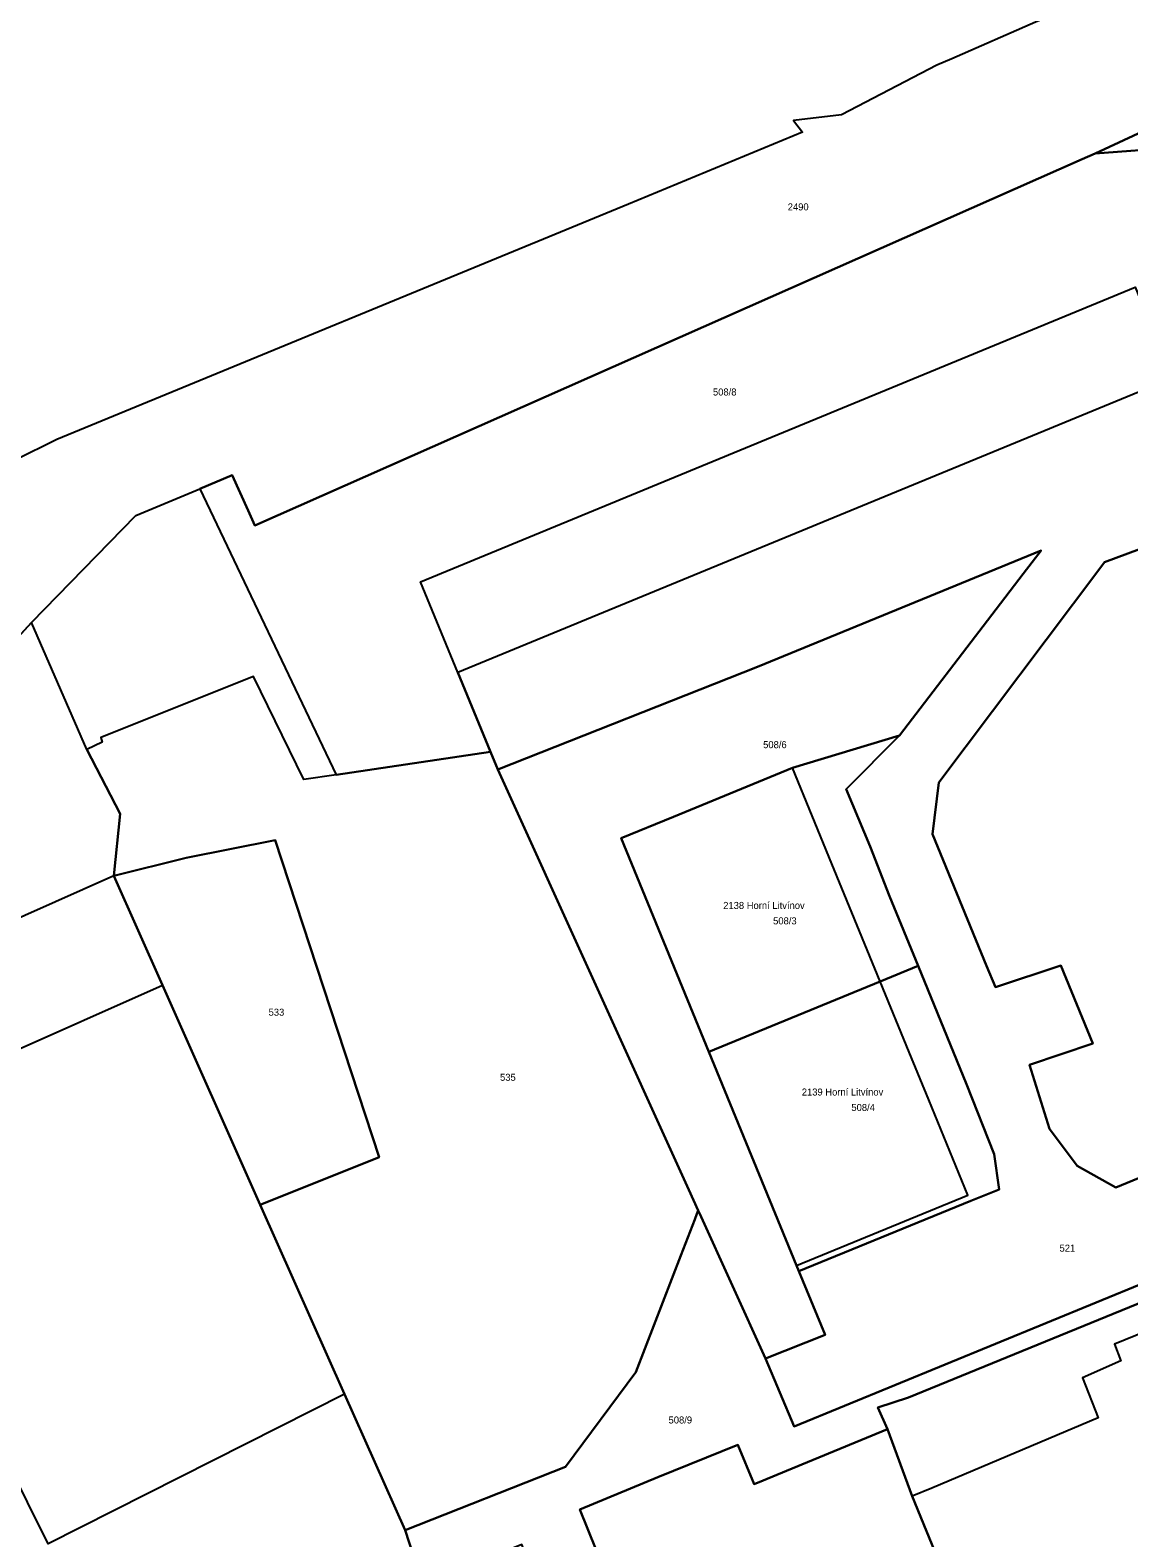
# Model space of a CAD drawing. Extents: x -792094 to -791524, y -979074 to -977761.
# Drawn here: x -791873.9 to -791795.7, y -978554.8 to -978447.5 of the extents above; entities that cross this region are included whole.
import ezdxf

# ---------------------------------------------------------------- set-up
doc = ezdxf.new("R2010")
doc.units = 0
doc.layers.add('katastr', color=7, linetype='Continuous')

msp = doc.modelspace()

# ---------------------------------------------------------------- linework, layer by layer
at = {"layer": 'katastr'}
for points in [[(-791795.52, -978444.13), (-791797.38, -978444.82), (-791798.74, -978445.45), (-791799.89, -978445.93), (-791801.55, -978446.63), (-791802.38, -978446.98), (-791808.34, -978449.57), (-791809.4, -978450.03), (-791816.2, -978453.56), (-791819.61, -978453.96), (-791818.96, -978454.81), (-791831.35, -978459.92), (-791872.03, -978476.67), (-791875, -978478.14)], [(-791881.47, -978498.04), (-791873.83, -978489.7), (-791866.4, -978482.08), (-791861.86, -978480.18), (-791859.55, -978479.21), (-791858.41, -978481.73), (-791857.93, -978482.79), (-791799.08, -978456.73), (-791798.15, -978456.32), (-791780.49, -978448.1)], [(-791780.49, -978448.1), (-791798.15, -978456.32), (-791792.44, -978455.89)], [(-791792.64, -978472.3), (-791843.49, -978493.26), (-791841.16, -978498.91), (-791840.65, -978500.15), (-791822.17, -978492.85), (-791801.99, -978484.56), (-791803.27, -978486.24), (-791805.49, -978489.15), (-791812.06, -978497.74), (-791815.87, -978501.56), (-791814.16, -978505.64), (-791812.78, -978509.16), (-791810.75, -978514.13), (-791808.68, -978519.19), (-791807.31, -978522.56), (-791805.34, -978527.53), (-791804.98, -978530.04), (-791806.99, -978530.86), (-791819.22, -978535.87), (-791817.36, -978540.4), (-791821.61, -978542.07), (-791819.57, -978546.91), (-791769.41, -978526.33)], [(-791792.51, -978483.54), (-791797.47, -978485.4), (-791797.82, -978485.86), (-791809.28, -978501.08), (-791809.72, -978504.77), (-791805.88, -978514.12), (-791805.24, -978515.64), (-791800.59, -978514.11), (-791798.32, -978519.66), (-791802.81, -978521.18), (-791801.39, -978525.72), (-791799.42, -978528.37), (-791796.68, -978529.91), (-791780.67, -978523.32)], [(-791780.67, -978523.32), (-791796.68, -978529.91), (-791799.42, -978528.37), (-791801.39, -978525.72), (-791802.81, -978521.18), (-791798.32, -978519.66), (-791800.59, -978514.11), (-791805.24, -978515.64), (-791805.88, -978514.12), (-791809.72, -978504.77), (-791809.28, -978501.08), (-791797.82, -978485.86), (-791797.47, -978485.4), (-791792.51, -978483.54)], [(-791875, -978589.26), (-791840.39, -978574.85), (-791842.83, -978568.27), (-791842.3, -978568.03), (-791845.28, -978560.36), (-791847.25, -978554.3), (-791851.56, -978544.62), (-791857.55, -978531.14), (-791864.51, -978515.5), (-791867.96, -978507.73), (-791867.52, -978503.3), (-791869.9, -978498.73), (-791873.83, -978489.7), (-791881.47, -978498.04)], [(-791769.41, -978526.33), (-791819.57, -978546.91), (-791821.61, -978542.07), (-791826.31, -978531.72), (-791826.39, -978531.54), (-791826.48, -978531.79), (-791826.64, -978532.19), (-791827.63, -978534.75), (-791830.84, -978543.04), (-791835.83, -978549.79), (-791847.25, -978554.3), (-791845.28, -978560.36)], [(-791833.68, -978555.64), (-791834.82, -978552.82), (-791829.26, -978550.53), (-791823.58, -978548.22), (-791822.41, -978551.01), (-791821.77, -978550.75), (-791820.1, -978550.06), (-791812.93, -978547.11), (-791813.62, -978545.56), (-791811.43, -978544.86), (-791774.63, -978529.81)], [(-791789.81, -978538.22), (-791796.77, -978541.06), (-791796.33, -978542.25), (-791799.04, -978543.45), (-791797.94, -978546.29), (-791809.76, -978551.3), (-791811.16, -978551.87), (-791807.29, -978561.32)]]:
    msp.add_lwpolyline(points, dxfattribs=at)
for points in [[(-791852.16, -978500.54), (-791841.16, -978498.91), (-791843.49, -978493.26), (-791846.16, -978486.79), (-791795.31, -978465.83), (-791792.64, -978472.3), (-791790.63, -978473.64), (-791787.06, -978473.52), (-791785.07, -978470.7), (-791784.46, -978468.6), (-791784.9, -978465.65), (-791787.73, -978459.17), (-791790.15, -978456.83), (-791792.44, -978455.89), (-791798.15, -978456.32), (-791799.08, -978456.73), (-791857.93, -978482.79), (-791858.41, -978481.73), (-791859.55, -978479.21), (-791861.86, -978480.18)], [(-791817.36, -978540.4), (-791819.22, -978535.87), (-791819.39, -978535.45), (-791825.63, -978520.24), (-791831.87, -978505.05), (-791828.14, -978503.52), (-791826.93, -978503.02), (-791819.69, -978500.04), (-791812.06, -978497.74), (-791805.49, -978489.15), (-791803.27, -978486.24), (-791801.99, -978484.56), (-791822.17, -978492.85), (-791840.65, -978500.15), (-791827.05, -978530.08), (-791826.39, -978531.54), (-791826.31, -978531.72), (-791821.61, -978542.07)], [(-791857.55, -978531.14), (-791851.56, -978544.62), (-791847.25, -978554.3), (-791835.83, -978549.79), (-791830.84, -978543.04), (-791827.63, -978534.75), (-791826.64, -978532.19), (-791826.48, -978531.79), (-791826.39, -978531.54), (-791827.05, -978530.08), (-791840.65, -978500.15), (-791841.16, -978498.91), (-791852.16, -978500.54), (-791854.45, -978500.88), (-791858.03, -978493.54), (-791868.89, -978497.87), (-791868.79, -978498.21), (-791869.9, -978498.73), (-791867.52, -978503.3), (-791867.96, -978507.73), (-791862.83, -978506.45), (-791856.48, -978505.18), (-791849.09, -978527.74)], [(-791815.87, -978501.56), (-791812.06, -978497.74), (-791819.69, -978500.04), (-791826.93, -978503.02), (-791828.14, -978503.52), (-791831.87, -978505.05), (-791825.63, -978520.24), (-791813.45, -978515.24), (-791810.75, -978514.13), (-791812.78, -978509.16), (-791814.16, -978505.64)], [(-791816.88, -978506.87), (-791819.69, -978500.04), (-791826.93, -978503.02), (-791828.14, -978503.52), (-791831.87, -978505.05), (-791825.63, -978520.24), (-791813.45, -978515.24), (-791815.46, -978510.33)], [(-791856.48, -978505.18), (-791862.83, -978506.45), (-791867.96, -978507.73), (-791864.51, -978515.5), (-791857.55, -978531.14), (-791849.09, -978527.74)], [(-791895.64, -978523.92), (-791904.12, -978527.7), (-791898.74, -978539.79), (-791896.4, -978545.04), (-791894.73, -978548.78), (-791888.92, -978561.85), (-791886.45, -978560.75), (-791876.4, -978583.26), (-791842.83, -978568.27), (-791842.3, -978568.03), (-791845.28, -978560.36), (-791847.25, -978554.3), (-791851.56, -978544.62), (-791872.65, -978555.27), (-791887.35, -978525.65), (-791864.51, -978515.5), (-791867.96, -978507.73), (-791890.94, -978517.95), (-791889.5, -978521.19)], [(-791825.63, -978520.24), (-791819.39, -978535.45), (-791819.22, -978535.87), (-791806.99, -978530.86), (-791804.98, -978530.04), (-791805.34, -978527.53), (-791807.31, -978522.56), (-791808.68, -978519.19), (-791810.75, -978514.13), (-791813.45, -978515.24)], [(-791809.99, -978523.66), (-791811.37, -978520.28), (-791813.45, -978515.24), (-791825.63, -978520.24), (-791819.39, -978535.45), (-791807.2, -978530.44)], [(-791771.33, -978535.31), (-791774.63, -978529.81), (-791811.43, -978544.86), (-791813.62, -978545.56), (-791812.93, -978547.11), (-791811.16, -978551.87), (-791807.29, -978561.32), (-791796.91, -978557.01), (-791797.13, -978556.47), (-791790.51, -978553.7), (-791790.37, -978554.03), (-791785.57, -978552.04), (-791785.71, -978551.71), (-791779.05, -978548.94), (-791778.82, -978549.5), (-791768.52, -978545.22), (-791771.39, -978535.79), (-791771.11, -978535.68)], [(-791833.68, -978555.64), (-791838.1, -978557.39), (-791838.94, -978555.31), (-791842.27, -978556.66), (-791841.45, -978558.73), (-791845.28, -978560.36), (-791842.3, -978568.03), (-791839.7, -978574.57), (-791824.14, -978568.2), (-791807.29, -978561.32), (-791811.16, -978551.87), (-791812.93, -978547.11), (-791820.1, -978550.06), (-791821.77, -978550.75), (-791822.41, -978551.01), (-791823.58, -978548.22), (-791829.26, -978550.53), (-791834.82, -978552.82)], [(-791807.29, -978561.32), (-791811.16, -978551.87), (-791812.93, -978547.11), (-791820.1, -978550.06), (-791821.77, -978550.75), (-791822.41, -978551.01), (-791823.58, -978548.22), (-791829.26, -978550.53), (-791834.82, -978552.82), (-791833.68, -978555.64), (-791838.1, -978557.39), (-791838.94, -978555.31), (-791842.27, -978556.66), (-791841.45, -978558.73), (-791845.28, -978560.36), (-791842.3, -978568.03), (-791839.7, -978574.57), (-791824.14, -978568.2)]]:
    msp.add_lwpolyline(points, close=True, dxfattribs=at)

# ---------------------------------------------------------------- texts
for s, p in [('2490', (-791820.02, -978460.37)), ('508/8', (-791825.34, -978473.54)), ('508/6', (-791821.77, -978498.64)), ('2138 Horní Litvínov', (-791824.61, -978510.08)), ('508/3', (-791821.06, -978511.18)), ('533', (-791856.96, -978517.68)), ('535', (-791840.49, -978522.31)), ('2139 Horní Litvínov', (-791819.02, -978523.36)), ('508/4', (-791815.49, -978524.46)), ('521', (-791800.68, -978534.47)), ('508/9', (-791828.5, -978546.7))]:
    msp.add_text(s, height=0.5, dxfattribs=at).set_placement(p)

doc.saveas('drawing.dxf')
